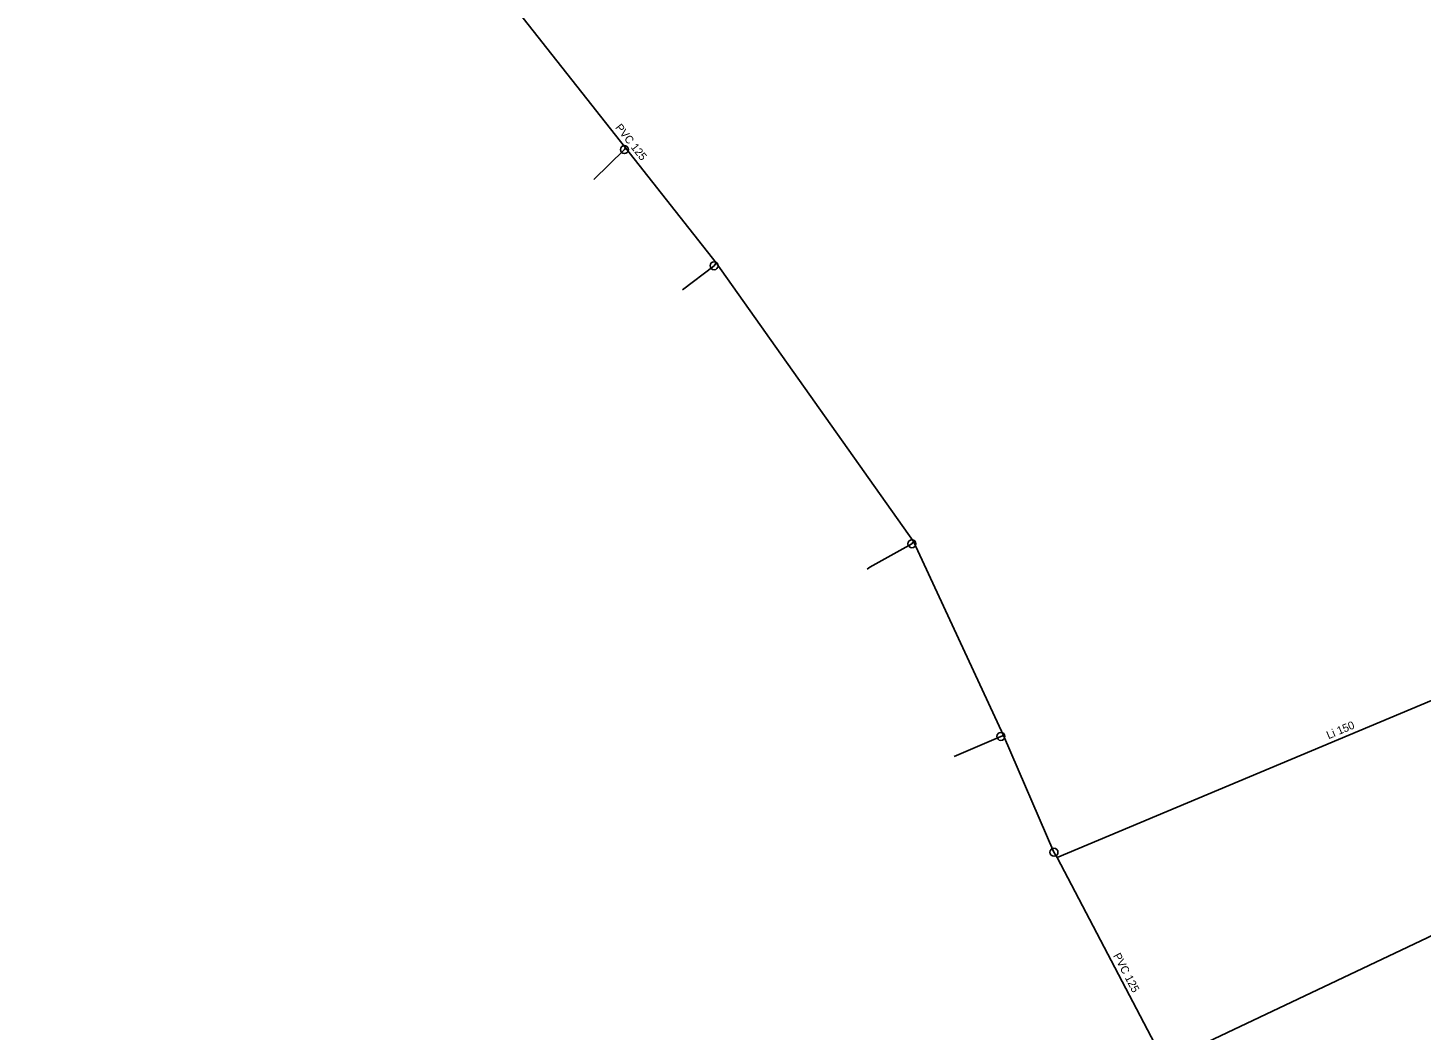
# Model space of a CAD drawing. Extents: x -684724 to -684366, y -1163865 to -1163489.
# Drawn here: x -684582.3 to -684495.3, y -1163776.1 to -1163713.4 of the extents above; entities that cross this region are included whole.
import ezdxf

# ---------------------------------------------------------------- set-up
doc = ezdxf.new("R2010")
doc.units = 0
for name, color, linetype in [('Popis vodovodních řadů', 7, 'Continuous'), ('Vod přípojky-voda pitná', 7, 'Continuous'), ('Vodovodní řad', 7, 'Continuous'), ('Vodovodní šoupata', 7, 'Continuous')]:
    doc.layers.add(name, color=color, linetype=linetype)

msp = doc.modelspace()

# ---------------------------------------------------------------- linework, layer by layer
at = {"layer": 'Vod přípojky-voda pitná'}
for points in [[(-684544.98, -1163720.91), (-684545.05, -1163721.03), (-684546.95, -1163722.9)], [(-684539.31, -1163728.11), (-684539.44, -1163728.29), (-684541.41, -1163729.8)], [(-684526.97, -1163745.53), (-684527.08, -1163745.67), (-684529.7, -1163747.12), (-684529.88, -1163747.25)], [(-684521.35, -1163757.65), (-684521.52, -1163757.71), (-684524.43, -1163758.97)]]:
    msp.add_lwpolyline(points, dxfattribs=at)
at = {"layer": 'Vodovodní řad'}
for points in [[(-684582.33, -1163681.24), (-684581.78, -1163681.69), (-684569.83, -1163692.53), (-684563.9, -1163698.27), (-684559.25, -1163703.63), (-684553.2, -1163710.61), (-684552.01, -1163712.03), (-684544.98, -1163720.91), (-684539.31, -1163728.11), (-684526.97, -1163745.53), (-684521.35, -1163757.65), (-684518.2, -1163764.95)], [(-684483.88, -1163750.96), (-684518.01, -1163765.28)], [(-684473.97, -1163760.15), (-684474.96, -1163760.85), (-684476.34, -1163761.11), (-684481.86, -1163763.54), (-684494.87, -1163770.29), (-684511.01, -1163777.95)], [(-684518.01, -1163765.28), (-684518.2, -1163764.95)], [(-684518.01, -1163765.28), (-684511.46, -1163777.76)]]:
    msp.add_lwpolyline(points, dxfattribs=at)
at = {"layer": 'Vodovodní šoupata'}
for centre in [(-684545.05, -1163721.03), (-684539.44, -1163728.29), (-684527.08, -1163745.67), (-684521.52, -1163757.71), (-684518.2, -1163764.95)]:
    msp.add_circle(centre, 0.25, dxfattribs=at)

# ---------------------------------------------------------------- texts
at = {"layer": 'Popis vodovodních řadů'}
for s, rotation, p in [('PVC 125', 308.36749, (-684545.649, -1163719.662)), ('Li 150', 22.76157, (-684501.042, -1163757.889)), ('PVC 125', 297.69227, (-684514.514, -1163771.404))]:
    msp.add_text(s, height=0.5, rotation=rotation, dxfattribs=at).set_placement(p)

doc.saveas('drawing.dxf')
